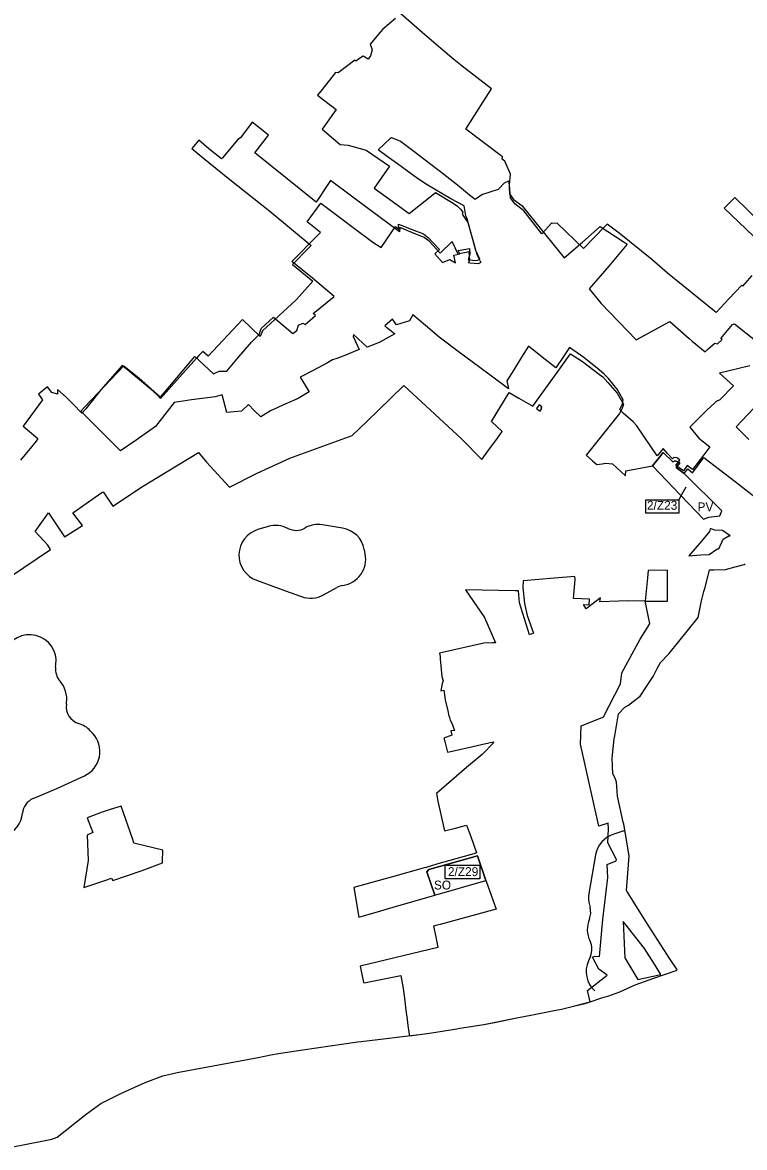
# Model space of a CAD drawing. Extents: x -445049 to -440454, y -1148980 to -1129741.
# Drawn here: x -442094 to -441281, y -1132776 to -1131508 of the extents above; entities that cross this region are included whole.
import ezdxf

# ---------------------------------------------------------------- set-up
doc = ezdxf.new("R2010")
doc.units = 0
for name, color, linetype in [('Vrstva 12', 7, 'Continuous'), ('Vrstva 23', 7, 'Continuous'), ('Vrstva 3', 7, 'Continuous'), ('Vrstva 4', 7, 'Continuous'), ('Vrstva 5', 7, 'Continuous'), ('Vrstva 7', 7, 'Continuous'), ('Vrstva 8', 7, 'Continuous')]:
    doc.layers.add(name, color=color, linetype=linetype)

msp = doc.modelspace()

# ---------------------------------------------------------------- linework, layer by layer
at = {"layer": 'Vrstva 12'}
for points in [[(-441772.9, -1131733.1), (-441757.6, -1131711.9), (-441735.1, -1131729), (-441718.4, -1131741.5), (-441702.2, -1131753.5), (-441699.1, -1131755.8), (-441689.8, -1131761.9), (-441673.7, -1131738.4), (-441669.7, -1131741.3), (-441670.3, -1131735.5), (-441656, -1131741.2), (-441642.1, -1131746.6), (-441636.5, -1131751), (-441631.5, -1131756.4), (-441624.1, -1131764.2), (-441629.4, -1131769), (-441620.7, -1131778.9), (-441612.4, -1131775.6), (-441605.9, -1131779.1), (-441607.7, -1131770.6), (-441601.1, -1131769.2), (-441602.9, -1131765.1), (-441590.2, -1131763.1), (-441589.9, -1131769.6), (-441591.6, -1131775.7), (-441582, -1131776.5), (-441578.4, -1131775.2), (-441583, -1131765.2), (-441592.7, -1131729.7), (-441594.4, -1131726.3), (-441596.3, -1131714.8), (-441611.3, -1131707), (-441637.9, -1131691.3), (-441648.7, -1131684.2), (-441671.4, -1131667.7), (-441681.4, -1131660.4), (-441693.1, -1131652), (-441679, -1131638.7), (-441678, -1131637.8), (-441668, -1131641.9), (-441652.9, -1131653.4), (-441635.2, -1131666.9), (-441624.5, -1131675.1), (-441603.6, -1131691.2), (-441590.4, -1131702.6), (-441583.8, -1131707.4), (-441576.3, -1131702.2), (-441557.6, -1131696.1), (-441550.8, -1131689.2), (-441545.8, -1131686.8), (-441545.2, -1131701.4), (-441540.8, -1131707.8), (-441531.1, -1131714.6), (-441510.7, -1131740.3), (-441483.7, -1131773.6), (-441463.1, -1131756), (-441463.1, -1131756), (-441442.9, -1131738.3), (-441417.2, -1131755.2), (-441412.7, -1131758.2), (-441433.4, -1131782.8), (-441455.3, -1131808.3), (-441441.9, -1131824.9), (-441402.5, -1131866.1), (-441364.8, -1131845.2), (-441342.7, -1131864.4), (-441339.4, -1131867.3), (-441325, -1131879.6), (-441321.4, -1131876.2), (-441314.1, -1131869.7), (-441310.8, -1131870.6), (-441305.8, -1131865.5), (-441307.2, -1131864.3), (-441293.9, -1131848.8), (-441291.7, -1131848), (-441268.2, -1131866.7)], [(-442023.9, -1131941.9), (-441979.5, -1131895.3), (-441962.6, -1131908.7), (-441938.2, -1131930.4), (-441899.4, -1131884.6), (-441878.4, -1131904.4), (-441872.3, -1131901.4), (-441863.3, -1131901.1), (-441852.3, -1131887.6), (-441835.7, -1131868.6), (-441827.2, -1131859.9), (-441824.8, -1131853.3), (-441811.1, -1131840.5), (-441789, -1131859), (-441784.8, -1131855.6), (-441782.6, -1131849.5), (-441778, -1131847), (-441775.4, -1131848.8), (-441763.5, -1131838.7), (-441766.1, -1131836.4), (-441742.5, -1131817.3), (-441767.2, -1131796.4), (-441790.3, -1131777.8), (-441760.2, -1131747.4), (-441758, -1131744.9), (-441772.9, -1131733.1)], [(-441546.4, -1131921), (-441550.8, -1131917.8), (-441580, -1131895.9), (-441599.8, -1131881.2), (-441624.3, -1131862.9), (-441639.8, -1131849.7), (-441654.1, -1131837.9), (-441657.9, -1131844.7), (-441672.6, -1131849.2), (-441676.8, -1131842.6), (-441685.4, -1131850.2), (-441674.2, -1131859.3), (-441691.1, -1131868.7), (-441697.6, -1131871.3), (-441705.4, -1131874.3), (-441720.8, -1131859.8), (-441721.4, -1131862.1), (-441714.3, -1131876.7), (-441720.7, -1131879.5), (-441728.8, -1131882.9), (-441739.7, -1131887.1), (-441744.5, -1131888.4), (-441750.3, -1131891.7), (-441766.2, -1131900.4), (-441780.9, -1131908.1), (-441770.6, -1131924.4), (-441783, -1131932.1), (-441797, -1131938.2), (-441814.2, -1131946.1), (-441825.3, -1131952.6), (-441832.7, -1131945.6), (-441839, -1131938.7), (-441847, -1131946.3), (-441863.5, -1131947.8), (-441868.8, -1131927.9), (-441876.6, -1131930.3), (-441885.4, -1131931.5), (-441903.1, -1131933.4), (-441922.9, -1131936.5), (-441922.9, -1131936.5), (-441928.2, -1131943.5), (-441943.7, -1131963.7), (-441965.6, -1131979.2), (-441983.4, -1131991.2), (-441987.1, -1131987.3), (-442012.5, -1131961.7), (-442028, -1131946.2), (-442023.9, -1131941.9)], [(-441274.5, -1131895.4), (-441308.8, -1131903.4), (-441293, -1131917.9), (-441308.2, -1131933.7), (-441312.5, -1131935.5), (-441314, -1131936.9), (-441323, -1131945.3), (-441342.1, -1131964.3), (-441332, -1131976.9), (-441319.6, -1131986.5), (-441326.5, -1131995.6), (-441339.2, -1132012.2), (-441345, -1132007.7), (-441349.2, -1132013.6), (-441357.9, -1132007.4), (-441353.5, -1132001.2), (-441356.6, -1131998.8), (-441360.2, -1131998.4), (-441361.6, -1132000.1), (-441367.2, -1131994), (-441372.2, -1131988.5), (-441378.7, -1131996.7), (-441401.6, -1131963), (-441405.8, -1131958.5), (-441417.1, -1131948.6), (-441421, -1131944.3), (-441418, -1131937.9), (-441417.2, -1131933.4), (-441424.1, -1131921.7), (-441433.7, -1131909.7), (-441438.6, -1131904.6), (-441444.3, -1131899.7), (-441461.5, -1131885.9), (-441477.7, -1131874.7), (-441484.5, -1131884.9), (-441492.9, -1131897.4), (-441508.5, -1131885.4), (-441523.9, -1131873.1), (-441531.5, -1131885.4), (-441540.4, -1131899.8), (-441548.2, -1131912.3), (-441546.4, -1131921)]]:
    msp.add_lwpolyline(points, dxfattribs=at)
at = {"layer": 'Vrstva 23'}
for p, q in [((-441816.9, -1132076.4), (-441828.4, -1132079.8)), ((-441794.6, -1132078.6), (-441794.8, -1132078.5)), ((-441733.3, -1132078.2), (-441755.9, -1132074.5)), ((-441707.6, -1132107.3), (-441708.6, -1132102.1)), ((-441830.1, -1132136.8), (-441793.3, -1132150.2)), ((-441754.6, -1132153.3), (-441739.6, -1132145)), ((-441793.3, -1132150.2), (-441779.4, -1132155.2)), ((-442056.3, -1132234.9), (-442055.9, -1132231.9)), ((-442044.2, -1132276.5), (-442044, -1132274.9)), ((-442014.5, -1132309.5), (-442017.3, -1132306.5)), ((-441419.9, -1132420.4), (-441427.7, -1132422.9)), ((-441448.2, -1132446.4), (-441455.7, -1132490)), ((-441455.2, -1132502.8), (-441454.4, -1132505.8)), ((-441454, -1132560.5), (-441456.3, -1132565.7))]:
    msp.add_line(p, q, dxfattribs=at)
msp.add_lwpolyline([(-442081.6, -1132383), (-442054.9, -1132371.5), (-442023.9, -1132357.2)], dxfattribs=at)
for centre, radius, start, end in [((-441819.9, -1132108.6), 30, 106.4691, 249.9908), ((-441808.4, -1132105.2), 30, 63.0188, 106.4691), ((-441785.6, -1132060.7), 20, 243.0188, 299.811), ((-441760.7, -1132104.1), 30, 80.8243, 119.811), ((-441738.1, -1132107.8), 30, 10.9833, 80.8243), ((-441737.1, -1132113), 30, 278.1919, 10.9833), ((-441729.9, -1132162.5), 20, 98.1919, 118.9801), ((-441783, -1132122), 30, 249.9908, 249.992), ((-441769.2, -1132127.1), 30, 249.992, 298.9801), ((-442085.7, -1132228.3), 30, 352.992, 159.0397), ((-442036.4, -1132237.3), 20, 172.992, 221.8345), ((-442073.7, -1132270.7), 30, 352.0222, 41.8345), ((-442024.4, -1132279.3), 20, 172.0222, 252.8379), ((-442039.2, -1132327), 30, 43.0849, 72.8379), ((-442036.4, -1132330), 30, 294.6949, 43.0849), ((-442073.7, -1132401.3), 20, 113.33, 174.3007), ((-442123.4, -1132396.4), 30, 290.6205, 354.3007), ((-441418.6, -1132451.5), 30, 107.6703, 170.1658), ((-441410.8, -1132449), 30, 99.6592, 107.6703), ((-441426.2, -1132495.2), 30, 170.1658, 194.7754), ((-441473.7, -1132510.9), 20, 337.1933, 14.7754), ((-441427.6, -1132530.3), 30, 157.1933, 206.4574), ((-441472.4, -1132552.6), 20, 336.5654, 26.4574), ((-441428.8, -1132577.7), 30, 156.5654, 227.4725)]:
    msp.add_arc(centre, radius, start, end, dxfattribs=at)
at = {"layer": 'Vrstva 3'}
msp.add_line((-441354.5, -1132046.1), (-441346.3, -1132031.5), dxfattribs=at)
for points in [[(-441391.7, -1132046.1), (-441354.5, -1132046.1), (-441354.5, -1132061.4), (-441391.7, -1132061.4)], [(-441617.7, -1132458.1), (-441578.7, -1132458.1), (-441578.7, -1132473.5), (-441617.7, -1132473.5)]]:
    msp.add_lwpolyline(points, close=True, dxfattribs=at)
at = {"layer": 'Vrstva 5'}
msp.add_lwpolyline([(-442108.4, -1132776.2), (-442066, -1132767.9), (-442060.5, -1132766.8), (-442054.5, -1132764.6), (-442021.8, -1132738.5), (-442005.4, -1132726.7), (-441983, -1132715.4), (-441955.6, -1132702.8), (-441935.6, -1132695.4), (-441919.5, -1132691.5), (-441828.1, -1132674.6), (-441813.9, -1132671.9), (-441805.4, -1132670.4), (-441778, -1132666.3), (-441716.2, -1132657.2), (-441712.3, -1132656.8), (-441643.6, -1132648.4), (-441635.1, -1132647.4), (-441604.5, -1132642.4), (-441601, -1132641.8), (-441573.9, -1132637.4), (-441562, -1132635.4), (-441537.1, -1132630.2), (-441519.4, -1132626.5), (-441496.9, -1132622.2), (-441486.5, -1132620.2), (-441471.6, -1132616.7), (-441460.1, -1132613.9), (-441454.2, -1132612), (-441441.3, -1132607.7), (-441433.3, -1132605.1), (-441421, -1132600.6), (-441403.6, -1132592.7), (-441382.8, -1132585.4), (-441356.3, -1132576.2), (-441356.6, -1132575.2), (-441364.5, -1132563.7), (-441391.7, -1132521.5), (-441405.8, -1132498.7), (-441413.3, -1132486.7), (-441410.6, -1132447.4), (-441416.6, -1132411.8), (-441417, -1132409.5), (-441423.5, -1132380.2), (-441424.6, -1132364.4), (-441426.3, -1132359.9), (-441428.7, -1132354.9), (-441429.5, -1132337.6), (-441427.2, -1132315.5), (-441426.6, -1132312.1), (-441422.3, -1132287.6), (-441415.2, -1132279.8), (-441411.1, -1132277.8), (-441405.9, -1132273.6), (-441398, -1132267.7), (-441390.2, -1132255.7), (-441383.3, -1132245.2), (-441378.8, -1132236.4), (-441375.2, -1132229.7), (-441365.5, -1132219.4), (-441332.6, -1132178.8), (-441328.8, -1132160.1), (-441326.2, -1132149.7), (-441325, -1132144.9), (-441320.1, -1132125.1), (-441315.2, -1132125), (-441302, -1132124.8), (-441291.2, -1132121.9), (-441280.8, -1132119.2), (-441279.9, -1132118.4)], dxfattribs=at)
at = {"layer": 'Vrstva 7'}
for points in [[(-441272.4, -1131793.4), (-441282.8, -1131805.4), (-441283.8, -1131804.6), (-441297.7, -1131819.4), (-441312.5, -1131835.2), (-441314.4, -1131833.7), (-441367.3, -1131790.8), (-441384.9, -1131775.6), (-441421.8, -1131745.6), (-441435.3, -1131735.6), (-441438, -1131738.3), (-441461.9, -1131763.2), (-441491.4, -1131734.3), (-441497.1, -1131735), (-441497.8, -1131734.4), (-441508.7, -1131746.5), (-441528.9, -1131720.4), (-441539.2, -1131712.8), (-441544.2, -1131705.9), (-441545, -1131691.1), (-441544, -1131679.2), (-441550.5, -1131664.5), (-441553.4, -1131662.4), (-441552.9, -1131659.9), (-441594.4, -1131628.6), (-441579.2, -1131604.8), (-441577.4, -1131602), (-441565.3, -1131583.2), (-441590.2, -1131563.9), (-441598.3, -1131557.7), (-441607.8, -1131550.1), (-441622.6, -1131537.5), (-441643.5, -1131519.6), (-441667.4, -1131498.7)], [(-441673.7, -1131503.7), (-441687.8, -1131515.9), (-441690.4, -1131518.7), (-441701.9, -1131532.6), (-441700, -1131539.3), (-441701.6, -1131545.9), (-441703.4, -1131548.6), (-441704.2, -1131549.5), (-441710, -1131546.4), (-441716.2, -1131550.5), (-441718.4, -1131551.9), (-441719.5, -1131550.9), (-441738.1, -1131565.2), (-441741.1, -1131564.8), (-441756.3, -1131584), (-441761.3, -1131590.4), (-441754.6, -1131595.5), (-441740.5, -1131606.4), (-441756.2, -1131628.6), (-441743.2, -1131639.4), (-441735.9, -1131645.7), (-441726.7, -1131646.6), (-441706.4, -1131652.3), (-441680.2, -1131670.4), (-441697.5, -1131695.2), (-441673.2, -1131712.8), (-441658.3, -1131723.6), (-441632.6, -1131703.4), (-441628.5, -1131700), (-441608.5, -1131711.8), (-441603.6, -1131715.5), (-441600.5, -1131718.6), (-441597.6, -1131722.2), (-441598.5, -1131724.3), (-441592, -1131733.6), (-441589.7, -1131741.8), (-441583.9, -1131763.1), (-441582.3, -1131769.1), (-441577.6, -1131778.7), (-441580.4, -1131780.3), (-441589.7, -1131779.4), (-441591.2, -1131779.3), (-441590, -1131776), (-441590.7, -1131766.9), (-441603, -1131769.4), (-441609.9, -1131755.1), (-441623.1, -1131768.2), (-441635.6, -1131754.7), (-441641.4, -1131750.5), (-441655.1, -1131744.9), (-441668.8, -1131739.4), (-441669.2, -1131744.3), (-441700.8, -1131720.7), (-441746.9, -1131686.4), (-441748.3, -1131688.6), (-441762.8, -1131710.8), (-441832.1, -1131655.2), (-441816.7, -1131635.2), (-441818.8, -1131633.6), (-441834.9, -1131620.5), (-441848.2, -1131638.3), (-441851.2, -1131640.2), (-441868.3, -1131660.7), (-441869.5, -1131661.9), (-441883.6, -1131650.6), (-441894.9, -1131641), (-441903, -1131650.3), (-441891.8, -1131659.9), (-441860.2, -1131685.1), (-441815.2, -1131720.9), (-441768.4, -1131759.5), (-441770, -1131761.2), (-441771, -1131762.2), (-441789.4, -1131781.1), (-441766.8, -1131799.7), (-441785.2, -1131820.6), (-441785.8, -1131821.2), (-441809.9, -1131843.5), (-441823.5, -1131856), (-441826, -1131862.1), (-441845.7, -1131843.2), (-441884.4, -1131884.5), (-441890.5, -1131879), (-441892, -1131880.6), (-441894.9, -1131883.8), (-441897.5, -1131886.8), (-441938.2, -1131932.1), (-441942.2, -1131927.5), (-441948.7, -1131922), (-441961.9, -1131911), (-441981.2, -1131895), (-442005.5, -1131922.3), (-442022.3, -1131943.6), (-442026.6, -1131948.5), (-442037, -1131937.9), (-442044.3, -1131930.4), (-442054, -1131921.9), (-442054.1, -1131927.1), (-442060.5, -1131925.4), (-442065.3, -1131919.1), (-442075.7, -1131927.2), (-442070.9, -1131933.5), (-442092.7, -1131963.2), (-442076.3, -1131977.2), (-442078.2, -1131980.1), (-442095.7, -1132001.5)], [(-441246.6, -1131749.2), (-441291.4, -1131705.6), (-441303.3, -1131717.5), (-441253.8, -1131764.8)], [(-442118.8, -1132140.7), (-442092.1, -1132122.5), (-442062, -1132102.1), (-442065, -1132097.4), (-442079.2, -1132081.9), (-442064.3, -1132061), (-442046.4, -1132087.9), (-442026.2, -1132075.2), (-442037, -1132060.8), (-442004.1, -1132038.1), (-442002.7, -1132037.1), (-441991.9, -1132053.5), (-441958.3, -1132031.1), (-441941.2, -1132020.7), (-441895.4, -1131992.8), (-441886.3, -1132004), (-441860.6, -1132031.9), (-441829.5, -1132016.1), (-441792.5, -1131999.5), (-441722.3, -1131973.6), (-441705.8, -1131958), (-441692.6, -1131945.4), (-441678.6, -1131931.4), (-441664, -1131917.5), (-441599.2, -1131977.5), (-441576.5, -1132000.7), (-441569.7, -1131991.4), (-441558.7, -1131976.6), (-441553.3, -1131969.3), (-441565.5, -1131958), (-441545.5, -1131925.3), (-441534.6, -1131931.6), (-441518.8, -1131940.8), (-441491.5, -1131902.7), (-441483.1, -1131891.1), (-441476.4, -1131881.8), (-441462.9, -1131890.2), (-441443.8, -1131905), (-441440.2, -1131907.8), (-441434.3, -1131913.9), (-441423.9, -1131926), (-441416.9, -1131938.3), (-441417.9, -1131942.2), (-441421.4, -1131948.8), (-441458.8, -1131995.8), (-441451.7, -1132002.2), (-441447, -1132006.5), (-441440.9, -1132005.8), (-441437, -1132004.9), (-441429.2, -1132005.7), (-441414.5, -1132019.1), (-441414.2, -1132013.6), (-441384, -1132008), (-441377.8, -1132000.1), (-441372.2, -1131992.9), (-441360.9, -1132003.9), (-441359.3, -1132002.2), (-441355, -1132003.4), (-441353.4, -1132004.7), (-441357.4, -1132009.9), (-441348.6, -1132016.7), (-441344.5, -1132011.4), (-441339, -1132015.7), (-441326.3, -1131998.7), (-441291.2, -1132025.8), (-441248.2, -1132059)], [(-441275.6, -1131978.1), (-441289.8, -1131963.9), (-441270.4, -1131943.3)], [(-441581.3, -1132447.6), (-441571.7, -1132475.1), (-441570.9, -1132477.3), (-441560.3, -1132507.6), (-441599.8, -1132518.5), (-441623.1, -1132524.8), (-441626.5, -1132525.7), (-441630.8, -1132526.9), (-441628.2, -1132538.9), (-441625.8, -1132550.8), (-441713.3, -1132571.9), (-441709.6, -1132590.2), (-441708.9, -1132590.5), (-441667.5, -1132582.3), (-441665, -1132596.9), (-441663.1, -1132610.9), (-441662.1, -1132618.5), (-441661.4, -1132624.2), (-441660.4, -1132631.8), (-441659.5, -1132638.6), (-441658.5, -1132646.2), (-441657.9, -1132650.2), (-441643.6, -1132648.4), (-441635.1, -1132647.4), (-441604.5, -1132642.4), (-441601, -1132641.8), (-441573.9, -1132637.4), (-441537.1, -1132630.2), (-441519.4, -1132626.5), (-441496.9, -1132622.2), (-441486.5, -1132620.2), (-441471.6, -1132616.7), (-441454.2, -1132612), (-441457.2, -1132599.4), (-441435.2, -1132581.9), (-441444.6, -1132575.2), (-441451.8, -1132561.7), (-441449, -1132560.6), (-441444, -1132560.9), (-441440.2, -1132519.2), (-441434.4, -1132471.9), (-441435.2, -1132457.3), (-441425, -1132453.2), (-441424.6, -1132451.8), (-441434.6, -1132432.7), (-441433.8, -1132416.9), (-441433.9, -1132410.8), (-441444.5, -1132413.9), (-441465.3, -1132321.8), (-441464.3, -1132301), (-441440.7, -1132291.4), (-441439.2, -1132290.8), (-441420.1, -1132253.7), (-441418.8, -1132241.1), (-441398.1, -1132203.3), (-441389.7, -1132190), (-441387, -1132185.5), (-441392.4, -1132160.4), (-441410.7, -1132160), (-441422.1, -1132160.4), (-441443.6, -1132161.2), (-441442.7, -1132156.9), (-441458.8, -1132169.2), (-441461.7, -1132164.4), (-441455.5, -1132164.7), (-441455.2, -1132158.3), (-441473, -1132157.3), (-441471.3, -1132136.2), (-441471.7, -1132132.8), (-441494.5, -1132134.7), (-441529.8, -1132137.7), (-441530.1, -1132145.2), (-441528.3, -1132163.2), (-441525.1, -1132176.6), (-441518.1, -1132196.5), (-441522.8, -1132198.4), (-441533.8, -1132162.2), (-441535, -1132149), (-441538.7, -1132148.9), (-441594.8, -1132147.6), (-441573.4, -1132178.7), (-441560.9, -1132207.4), (-441562.9, -1132207.5), (-441564.3, -1132207.6), (-441574.1, -1132208), (-441623.9, -1132219.1), (-441623.4, -1132222.9), (-441623.2, -1132225.4), (-441621.2, -1132245.5), (-441619.9, -1132250.2), (-441621.1, -1132253.1), (-441622.4, -1132261.7), (-441619.1, -1132260.8), (-441617.6, -1132271.7), (-441614.5, -1132284.2), (-441613.6, -1132290.1), (-441613.1, -1132290.1), (-441612, -1132294.5), (-441610, -1132298.1), (-441607.1, -1132306.3), (-441611.4, -1132306.6), (-441610.2, -1132311.5), (-441619, -1132314.7), (-441618, -1132318.6), (-441614.9, -1132330.6), (-441599.5, -1132327.1), (-441563.6, -1132319.1), (-441563, -1132319.8), (-441576, -1132333.2), (-441593.7, -1132348), (-441627.4, -1132377.3), (-441625.7, -1132385.8), (-441618.2, -1132419.3), (-441606.1, -1132416.2), (-441593.5, -1132412.8), (-441588.9, -1132425.7), (-441582.5, -1132444.1)], [(-441639.8, -1132460.8), (-441625.4, -1132456.3), (-441582.5, -1132444.1)], [(-441638.1, -1132465.7), (-441636.1, -1132463), (-441581.3, -1132447.6)], [(-441639.8, -1132460.8), (-441677.1, -1132471), (-441700.1, -1132477.5), (-441720.5, -1132483.3), (-441714.8, -1132516.6), (-441690.2, -1132509.6), (-441676, -1132505.5), (-441629.1, -1132492), (-441638.1, -1132465.7)]]:
    msp.add_lwpolyline(points, dxfattribs=at)
for points in [[(-441508.9, -1131941.5), (-441511.8, -1131939.2), (-441514.9, -1131943.2), (-441510.8, -1131946.3), (-441508.6, -1131943.5), (-441509.8, -1131942.6)], [(-441296.5, -1132086.8), (-441305.4, -1132081), (-441314, -1132080.3), (-441318.2, -1132079.1), (-441319.2, -1132078.8), (-441320.1, -1132082), (-441329.1, -1132092.8), (-441343.3, -1132109.5), (-441329.8, -1132108.1), (-441320.2, -1132107.8), (-441311.6, -1132101.8), (-441311.1, -1132101.4), (-441309.4, -1132101.4), (-441304.5, -1132090.6), (-441298.3, -1132087)], [(-441389, -1132126), (-441389.8, -1132134.1), (-441392.4, -1132160.4), (-441388.5, -1132160.4), (-441367.2, -1132160.4), (-441367.2, -1132141), (-441367.1, -1132125.6)], [(-441982.5, -1132391.4), (-441995, -1132395.4), (-442003.9, -1132398.3), (-442020.9, -1132404.5), (-442014.3, -1132421.3), (-442020.6, -1132424.1), (-442019.7, -1132452.7), (-442024.6, -1132483.2), (-442000.9, -1132475.3), (-441993.2, -1132472.7), (-441991.9, -1132475.1), (-441958.9, -1132464.1), (-441935.9, -1132455.3), (-441935.9, -1132453.9), (-441935.4, -1132441.2), (-441968.1, -1132433.2), (-441969.5, -1132429.2)], [(-441417.2, -1132521.4), (-441415.4, -1132562.3), (-441400.8, -1132586.8), (-441374.8, -1132581.3), (-441381.8, -1132569.4), (-441393.2, -1132552.1), (-441394.8, -1132550), (-441413.7, -1132525.8)]]:
    msp.add_lwpolyline(points, close=True, dxfattribs=at)
at = {"layer": 'Vrstva 8'}
for points in [[(-441348.6, -1132016.7), (-441357.4, -1132009.9), (-441353.4, -1132004.7), (-441355, -1132003.4), (-441359.3, -1132002.2), (-441360.9, -1132003.9), (-441372.2, -1131992.9), (-441377.8, -1132000.1), (-441384, -1132008), (-441352.2, -1132041.4), (-441326.8, -1132067.9), (-441320.6, -1132065.8), (-441308.5, -1132064.4), (-441305.9, -1132058.6)], [(-441581.3, -1132447.6), (-441636.1, -1132463), (-441638.1, -1132465.7), (-441637.4, -1132467.7), (-441629.1, -1132492), (-441571.7, -1132475.1), (-441580.5, -1132449.8)]]:
    msp.add_lwpolyline(points, close=True, dxfattribs=at)

# ---------------------------------------------------------------- texts
at = {"layer": 'Vrstva 3'}
for s, p in [('2/Z23', (-441390.4, -1132057.5)), ('2/Z29', (-441614.5, -1132470.3))]:
    msp.add_text(s, height=10, dxfattribs=at).set_placement(p)
at = {"layer": 'Vrstva 4'}
for s, p in [('PV', (-441333.4, -1132059.2)), ('SO', (-441630.3, -1132485.4))]:
    msp.add_text(s, height=10, dxfattribs=at).set_placement(p)

doc.saveas('drawing.dxf')
